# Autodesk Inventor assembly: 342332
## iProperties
Company: Hundt & Weber AG Schaltgeräte
Created: 2006-01
Part Number: 342332
Document SubType Name: Assembly
Designer: I.Baliuc
Manufacturer: Standard
Standards Organization: Custom
Description: Spule
Mass: 769.163 g
Surface Area: 1205.53 cm^2
Volume: 87.1497 cm^3
Density: 8.82576 g/cm^3
Zweck: für Blasspule
Author: I.Baliuc
Revision Number: 342332
